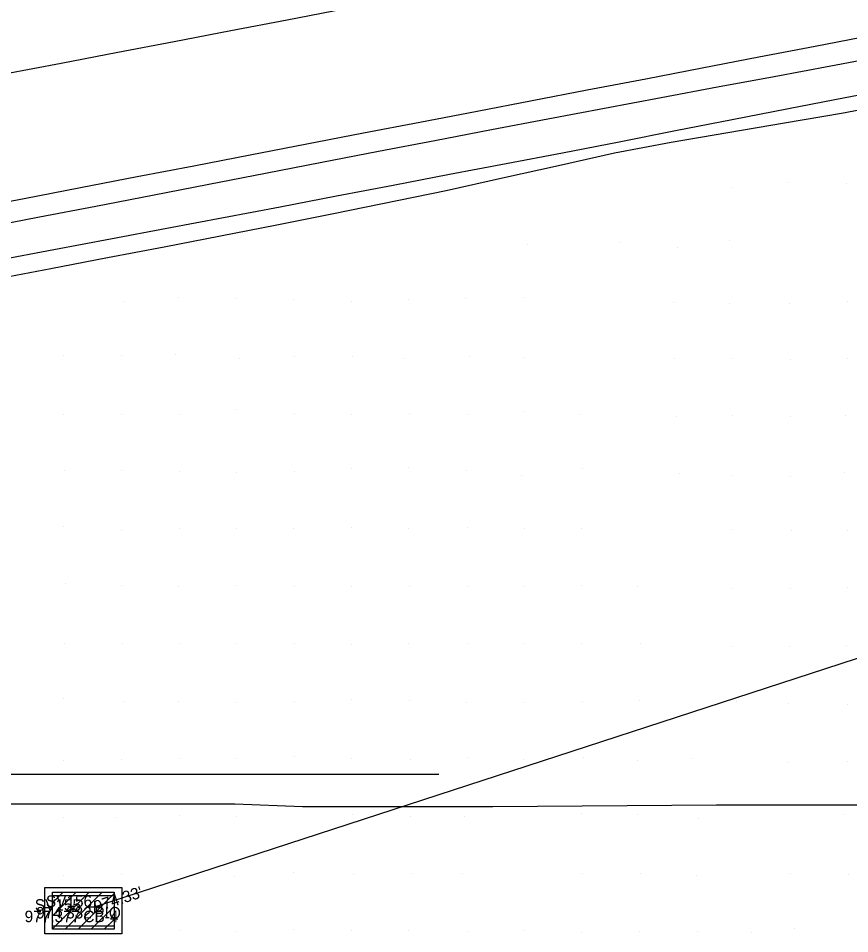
# Model space of a CAD drawing. Extents: x 2262025 to 2264532, y 740981 to 742724.
# Drawn here: x 2262948.6 to 2263020.8, y 742045.7 to 742125.3 of the extents above; entities that cross this region are included whole.
import ezdxf

# ---------------------------------------------------------------- set-up
doc = ezdxf.new("R2010")
doc.units = 0
for name, color, linetype in [('DR_X_Storm_Sewer', 7, 'Continuous'), ('GE_X_Alignment_1000_Curve_Data', 7, 'Continuous'), ('GE_X_Alignment_100_Cardinal_Points', 7, 'Continuous'), ('GE_X_Alignment_100_Curve_Data', 7, 'Continuous'), ('Ground Shots', 7, 'Continuous'), ('HY_X_Spring_Cells', 7, 'Continuous'), ('RS_Raster1', 7, 'Continuous'), ('RW_X_CL', 7, 'Continuous'), ('RW_X_CL_1000_Distances', 7, 'Continuous'), ('RW_X_CL_100_Curve_Data', 7, 'Continuous'), ('RW_X_CL_100_Stations', 7, 'Continuous'), ('RW_X_CL_500_Bearings', 7, 'Continuous'), ('SC_Scratch2', 7, 'Continuous'), ('SV_X_Control_Cells_Found', 7, 'Continuous'), ('SV_X_Text_Comment', 7, 'Continuous')]:
    doc.layers.add(name, color=color, linetype=linetype)

msp = doc.modelspace()

# ---------------------------------------------------------------- linework, layer by layer
at = {"layer": 'DR_X_Storm_Sewer'}
msp.add_line((2262955.205, 742048.032), (2263118.436, 742101.27), dxfattribs=at)
at = {"layer": 'GE_X_Alignment_1000_Curve_Data'}
msp.add_lwpolyline([(2262945.528, 742107.036), (2262950.437, 742107.987), (2262955.345, 742108.938), (2262960.254, 742109.889), (2262965.163, 742110.841), (2262970.072, 742111.792), (2262974.98, 742112.743), (2262979.889, 742113.694), (2262984.798, 742114.645), (2262989.706, 742115.597), (2262994.62, 742116.522), (2262999.535, 742117.442), (2263004.449, 742118.362), (2263009.364, 742119.282), (2263014.278, 742120.202), (2263019.193, 742121.122), (2263024.108, 742122.042)], dxfattribs=at)
at = {"layer": 'GE_X_Alignment_100_Cardinal_Points'}
msp.add_lwpolyline([(2262985.13, 742059.549), (2262938.943, 742059.549), (2262935.634, 742059.549), (2262925.641, 742058.739), (2262915.985, 742057.658), (2262904.843, 742055.901), (2262894.984, 742054.009), (2262882.695, 742051.644), (2262877.968, 742050.36), (2262877.968, 742048.671), (2262884.18, 742049.482), (2262893.026, 742051.104), (2262909.232, 742054.077), (2262920.847, 742055.698), (2262925.197, 742056.142), (2262929.094, 742056.605), (2262932.699, 742056.765), (2262937.682, 742056.986), (2262967.426, 742056.986), (2262973.291, 742056.765), (2262989.828, 742056.765), (2263009.27, 742056.896), (2263029.372, 742056.896)], dxfattribs=at)
at = {"layer": 'GE_X_Alignment_100_Curve_Data'}
msp.add_lwpolyline([(2263025.337, 742119.28), (2263020.429, 742118.33), (2263015.52, 742117.378), (2263010.612, 742116.427), (2263005.706, 742115.464), (2263000.801, 742114.495), (2262995.892, 742113.545), (2262990.981, 742112.606), (2262986.07, 742111.668), (2262981.159, 742110.729), (2262976.248, 742109.79), (2262971.337, 742108.851), (2262966.425, 742107.918), (2262961.513, 742106.989), (2262956.6, 742106.059), (2262951.687, 742105.129), (2262946.776, 742104.192)], dxfattribs=at)
at = {"layer": 'Ground Shots'}
for p, q in [((2263015.523, 742110.984), (2263015.523, 742110.984)), ((2263020.585, 742110.899), (2263020.585, 742110.899)), ((2263010.676, 742110.509), (2263010.676, 742110.509)), ((2263010.361, 742105.985), (2263010.361, 742105.985)), ((2262992.804, 742105.616), (2262992.804, 742105.616)), ((2263000.942, 742105.785), (2263000.942, 742105.785)), ((2263005.844, 742105.353), (2263005.844, 742105.353)), ((2262957.724, 742100.621), (2262957.724, 742100.621)), ((2262962.544, 742101.015), (2262962.544, 742101.015)), ((2262967.547, 742100.868), (2262967.547, 742100.868)), ((2262972.485, 742100.841), (2262972.485, 742100.841)), ((2262977.59, 742100.678), (2262977.59, 742100.678)), ((2262982.52, 742100.817), (2262982.52, 742100.817)), ((2262987.454, 742100.918), (2262987.454, 742100.918)), ((2262992.529, 742100.948), (2262992.529, 742100.948)), ((2263005.567, 742100.582), (2263005.567, 742100.582)), ((2263010.359, 742100.455), (2263010.359, 742100.455)), ((2263015.563, 742100.509), (2263015.563, 742100.509)), ((2263020.604, 742100.683), (2263020.604, 742100.683)), ((2262952.535, 742095.955), (2262952.535, 742095.955)), ((2262957.553, 742095.994), (2262957.553, 742095.994)), ((2262962.229, 742096.061), (2262962.229, 742096.061)), ((2262967.805, 742095.66), (2262967.805, 742095.66)), ((2262972.561, 742095.873), (2262972.561, 742095.873)), ((2262977.627, 742095.852), (2262977.627, 742095.852)), ((2262982.16, 742095.717), (2262982.16, 742095.717)), ((2262987.806, 742095.904), (2262987.806, 742095.904)), ((2262992.503, 742095.81), (2262992.503, 742095.81)), ((2263005.65, 742095.725), (2263005.65, 742095.725)), ((2263010.537, 742095.669), (2263010.537, 742095.669)), ((2263015.674, 742095.638), (2263015.674, 742095.638)), ((2263020.614, 742095.723), (2263020.614, 742095.723)), ((2262952.56, 742090.842), (2262952.56, 742090.842)), ((2262957.532, 742090.839), (2262957.532, 742090.839)), ((2262962.598, 742090.846), (2262962.598, 742090.846)), ((2262967.548, 742091.236), (2262967.548, 742091.236)), ((2262972.564, 742090.892), (2262972.564, 742090.892)), ((2262982.623, 742090.884), (2262982.623, 742090.884)), ((2262992.527, 742091.088), (2262992.527, 742091.088)), ((2262997.325, 742090.86), (2262997.325, 742090.86)), ((2262977.589, 742090.792), (2262977.589, 742090.792)), ((2262987.689, 742090.782), (2262987.689, 742090.782)), ((2263005.812, 742090.651), (2263005.812, 742090.651)), ((2263010.665, 742090.763), (2263010.665, 742090.763)), ((2263015.722, 742090.684), (2263015.722, 742090.684)), ((2263020.509, 742090.733), (2263020.509, 742090.733)), ((2262977.539, 742086.152), (2262977.539, 742086.152)), ((2262982.499, 742086.255), (2262982.499, 742086.255)), ((2262997.626, 742086.146), (2262997.626, 742086.146)), ((2262952.592, 742085.918), (2262952.592, 742085.918)), ((2262957.569, 742085.931), (2262957.569, 742085.931)), ((2262962.562, 742085.882), (2262962.562, 742085.882)), ((2262967.595, 742085.827), (2262967.595, 742085.827)), ((2262972.566, 742085.87), (2262972.566, 742085.87)), ((2262987.568, 742085.943), (2262987.568, 742085.943)), ((2262992.357, 742085.555), (2262992.357, 742085.555)), ((2263006.018, 742085.699), (2263006.018, 742085.699)), ((2263010.693, 742085.489), (2263010.693, 742085.489)), ((2263015.732, 742085.437), (2263015.732, 742085.437)), ((2263020.37, 742085.75), (2263020.37, 742085.75)), ((2262952.54, 742081.106), (2262952.54, 742081.106)), ((2262957.538, 742080.756), (2262957.538, 742080.756)), ((2262962.606, 742080.909), (2262962.606, 742080.909)), ((2262967.556, 742080.947), (2262967.556, 742080.947)), ((2262972.518, 742080.926), (2262972.518, 742080.926)), ((2262977.567, 742080.963), (2262977.567, 742080.963)), ((2262982.528, 742080.917), (2262982.528, 742080.917)), ((2262987.648, 742081.031), (2262987.648, 742081.031)), ((2262992.562, 742080.894), (2262992.562, 742080.894)), ((2262997.506, 742080.935), (2262997.506, 742080.935)), ((2263010.65, 742080.807), (2263010.65, 742080.807)), ((2263015.748, 742080.707), (2263015.748, 742080.707)), ((2263020.639, 742080.745), (2263020.639, 742080.745)), ((2262952.659, 742076.138), (2262952.659, 742076.138)), ((2262957.543, 742075.948), (2262957.543, 742075.948)), ((2262962.532, 742075.914), (2262962.532, 742075.914)), ((2262967.563, 742075.926), (2262967.563, 742075.926)), ((2262972.57, 742075.897), (2262972.57, 742075.897)), ((2262977.565, 742075.885), (2262977.565, 742075.885)), ((2262982.616, 742075.881), (2262982.616, 742075.881)), ((2262987.596, 742075.907), (2262987.596, 742075.907)), ((2262992.535, 742075.917), (2262992.535, 742075.917)), ((2262997.526, 742075.956), (2262997.526, 742075.956)), ((2263002.442, 742075.866), (2263002.442, 742075.866)), ((2263010.675, 742075.726), (2263010.675, 742075.726)), ((2263020.639, 742075.794), (2263020.639, 742075.794)), ((2263015.667, 742075.673), (2263015.667, 742075.673)), ((2262972.573, 742070.929), (2262972.573, 742070.929)), ((2262982.541, 742070.919), (2262982.541, 742070.919)), ((2262992.568, 742070.916), (2262992.568, 742070.916)), ((2262997.554, 742070.916), (2262997.554, 742070.916)), ((2262952.642, 742070.89), (2262952.642, 742070.89)), ((2262957.609, 742070.887), (2262957.609, 742070.887)), ((2262962.613, 742070.886), (2262962.613, 742070.886)), ((2262967.531, 742070.892), (2262967.531, 742070.892)), ((2262977.59, 742070.857), (2262977.59, 742070.857)), ((2262987.592, 742070.883), (2262987.592, 742070.883)), ((2263002.617, 742070.902), (2263002.617, 742070.902)), ((2263010.644, 742070.685), (2263010.644, 742070.685)), ((2263015.62, 742070.654), (2263015.62, 742070.654)), ((2263020.577, 742070.724), (2263020.577, 742070.724)), ((2262952.538, 742066.13), (2262952.538, 742066.13)), ((2262957.719, 742065.904), (2262957.719, 742065.904)), ((2262962.518, 742065.843), (2262962.518, 742065.843)), ((2262967.516, 742065.783), (2262967.516, 742065.783)), ((2262972.557, 742065.919), (2262972.557, 742065.919)), ((2262977.506, 742066.018), (2262977.506, 742066.018)), ((2262982.582, 742065.94), (2262982.582, 742065.94)), ((2262987.527, 742065.828), (2262987.527, 742065.828)), ((2262992.556, 742065.83), (2262992.556, 742065.83)), ((2262997.577, 742065.911), (2262997.577, 742065.911)), ((2263002.565, 742065.946), (2263002.565, 742065.946)), ((2263011.025, 742065.855), (2263011.025, 742065.855)), ((2263015.538, 742065.67), (2263015.538, 742065.67)), ((2263020.634, 742065.662), (2263020.634, 742065.662)), ((2262952.499, 742060.72), (2262952.499, 742060.72)), ((2262957.583, 742060.829), (2262957.583, 742060.829)), ((2262962.599, 742060.92), (2262962.599, 742060.92)), ((2262967.591, 742060.916), (2262967.591, 742060.916)), ((2262972.558, 742061.101), (2262972.558, 742061.101)), ((2262977.567, 742060.963), (2262977.567, 742060.963)), ((2262982.647, 742060.871), (2262982.647, 742060.871)), ((2262987.757, 742060.982), (2262987.757, 742060.982)), ((2262992.536, 742060.884), (2262992.536, 742060.884)), ((2262997.725, 742060.993), (2262997.725, 742060.993)), ((2263002.417, 742060.784), (2263002.417, 742060.784)), ((2263007.207, 742060.909), (2263007.207, 742060.909)), ((2263020.602, 742060.629), (2263020.602, 742060.629)), ((2263015.502, 742060.568), (2263015.502, 742060.568)), ((2262952.568, 742055.828), (2262952.568, 742055.828)), ((2262962.602, 742056.001), (2262962.602, 742056.001)), ((2262967.556, 742055.887), (2262967.556, 742055.887)), ((2262977.601, 742056.059), (2262977.601, 742056.059)), ((2262982.66, 742055.878), (2262982.66, 742055.878)), ((2262987.332, 742055.883), (2262987.332, 742055.883)), ((2262997.499, 742056.131), (2262997.499, 742056.131)), ((2263002.401, 742056.05), (2263002.401, 742056.05)), ((2263020.35, 742056.107), (2263020.35, 742056.107)), ((2262957.162, 742055.793), (2262957.162, 742055.793)), ((2263007.671, 742055.757), (2263007.671, 742055.757)), ((2262972.494, 742051.036), (2262972.494, 742051.036)), ((2262952.559, 742050.757), (2262952.559, 742050.757)), ((2262957.592, 742050.842), (2262957.592, 742050.842)), ((2262967.426, 742050.708), (2262967.426, 742050.708)), ((2262977.75, 742050.86), (2262977.75, 742050.86)), ((2262982.867, 742050.898), (2262982.867, 742050.898)), ((2262987.235, 742050.897), (2262987.235, 742050.897)), ((2262997.58, 742050.916), (2262997.58, 742050.916)), ((2263002.63, 742050.977), (2263002.63, 742050.977)), ((2263007.552, 742050.759), (2263007.552, 742050.759)), ((2263015.665, 742050.919), (2263015.665, 742050.919)), ((2263020.715, 742050.844), (2263020.715, 742050.844)), ((2262952.558, 742045.926), (2262952.558, 742045.926)), ((2262957.485, 742045.981), (2262957.485, 742045.981)), ((2262962.686, 742045.946), (2262962.686, 742045.946)), ((2262967.58, 742045.874), (2262967.58, 742045.874)), ((2262972.536, 742046.094), (2262972.536, 742046.094)), ((2262977.587, 742046.027), (2262977.587, 742046.027)), ((2262982.541, 742045.957), (2262982.541, 742045.957)), ((2262987.601, 742045.88), (2262987.601, 742045.88)), ((2262992.621, 742045.996), (2262992.621, 742045.996)), ((2262997.515, 742045.848), (2262997.515, 742045.848)), ((2263002.557, 742045.926), (2263002.557, 742045.926)), ((2263007.59, 742045.914), (2263007.59, 742045.914)), ((2263012.285, 742045.807), (2263012.285, 742045.807)), ((2263016.043, 742046.167), (2263016.043, 742046.167))]:
    msp.add_line(p, q, dxfattribs=at)
at = {"layer": 'RW_X_CL_1000_Distances'}
msp.add_lwpolyline([(2263022.754, 742123.758), (2263017.845, 742122.811), (2263012.935, 742121.865), (2263008.025, 742120.92), (2263003.115, 742119.975), (2262998.013, 742118.992), (2262993.256, 742118.077), (2262988.462, 742117.154), (2262983.476, 742116.194), (2262978.606, 742115.256), (2262973.656, 742114.303), (2262968.747, 742113.358), (2262963.837, 742112.413), (2262958.927, 742111.467), (2262954.017, 742110.522), (2262949.107, 742109.577), (2262944.197, 742108.632)], dxfattribs=at)
at = {"layer": 'RW_X_CL_100_Curve_Data'}
for p, q in [((2262951.584, 742046.141), (2262954.767, 742049.324)), ((2262951.584, 742047.273), (2262953.636, 742049.324)), ((2262951.584, 742048.404), (2262952.504, 742049.324)), ((2262951.584, 742046.141), (2262954.767, 742049.324)), ((2262951.584, 742047.273), (2262953.636, 742049.324)), ((2262951.584, 742048.404), (2262952.504, 742049.324)), ((2262952.669, 742046.095), (2262955.899, 742049.324)), ((2262952.669, 742046.095), (2262955.899, 742049.324)), ((2262953.801, 742046.095), (2262956.918, 742049.212)), ((2262953.801, 742046.095), (2262956.918, 742049.212)), ((2262954.932, 742046.095), (2262956.918, 742048.081)), ((2262954.932, 742046.095), (2262956.918, 742048.081)), ((2262956.063, 742046.095), (2262956.918, 742046.949)), ((2262956.063, 742046.095), (2262956.918, 742046.949))]:
    msp.add_line(p, q, dxfattribs=at)
for points in [[(2262950.918, 742049.71), (2262957.584, 742049.71), (2262957.584, 742045.71), (2262950.918, 742045.71)], [(2262950.918, 742049.71), (2262957.584, 742049.71), (2262957.584, 742045.71), (2262950.918, 742045.71)], [(2262951.584, 742049.324), (2262956.918, 742049.324), (2262956.918, 742046.095), (2262951.584, 742046.095)], [(2262951.584, 742049.324), (2262956.918, 742049.324), (2262956.918, 742046.095), (2262951.584, 742046.095)], [(2262951.584, 742049.043), (2262956.918, 742049.043), (2262956.918, 742046.377), (2262951.584, 742046.377)], [(2262951.584, 742049.043), (2262956.918, 742049.043), (2262956.918, 742046.377), (2262951.584, 742046.377)]]:
    msp.add_lwpolyline(points, close=True, dxfattribs=at)
at = {"layer": 'RW_X_CL_100_Stations'}
for p, q in [((2262954.251, 742049.71), (2262954.251, 742049.71)), ((2262954.251, 742049.71), (2262954.251, 742049.71)), ((2262954.251, 742049.043), (2262954.251, 742049.043)), ((2262954.251, 742049.043), (2262954.251, 742049.043)), ((2262951.584, 742047.71), (2262951.584, 742047.71)), ((2262951.584, 742047.71), (2262951.584, 742047.71)), ((2262954.251, 742047.71), (2262954.251, 742047.71)), ((2262954.251, 742047.71), (2262954.251, 742047.71)), ((2262954.251, 742047.71), (2262954.251, 742047.71)), ((2262954.251, 742047.71), (2262954.251, 742047.71)), ((2262956.918, 742047.71), (2262956.918, 742047.71)), ((2262956.918, 742047.71), (2262956.918, 742047.71)), ((2262954.251, 742046.377), (2262954.251, 742046.377)), ((2262954.251, 742046.377), (2262954.251, 742046.377)), ((2262954.251, 742046.095), (2262954.251, 742046.095)), ((2262954.251, 742046.095), (2262954.251, 742046.095)), ((2262954.251, 742045.71), (2262954.251, 742045.71)), ((2262954.251, 742045.71), (2262954.251, 742045.71))]:
    msp.add_line(p, q, dxfattribs=at)
at = {"layer": 'RW_X_CL_500_Bearings'}
for p, q in [((2262954.705, 742048.032), (2262955.705, 742048.032)), ((2262954.705, 742048.032), (2262955.705, 742048.032)), ((2262955.205, 742048.532), (2262955.205, 742047.532)), ((2262955.205, 742048.532), (2262955.205, 742047.532)), ((2262955.205, 742048.032), (2262955.205, 742048.032)), ((2262955.205, 742048.032), (2262955.205, 742048.032))]:
    msp.add_line(p, q, dxfattribs=at)
at = {"layer": 'SC_Scratch2'}
msp.add_lwpolyline([(2262976.874, 742126.032), (2262971.964, 742125.091), (2262967.053, 742124.15), (2262962.142, 742123.209), (2262957.232, 742122.267), (2262952.321, 742121.326), (2262947.411, 742120.385), (2262942.5, 742119.443), (2262937.589, 742118.502), (2262932.679, 742117.561), (2262927.768, 742116.619), (2262922.861, 742115.662), (2262917.954, 742114.703), (2262913.046, 742113.744), (2262908.139, 742112.784), (2262903.232, 742111.825), (2262898.325, 742110.865), (2262893.418, 742109.906), (2262888.511, 742108.947), (2262883.604, 742107.987), (2262878.697, 742107.028), (2262873.79, 742106.069)], dxfattribs=at)
at = {"layer": 'SV_X_Control_Cells_Found'}
msp.add_lwpolyline([(2262946.529, 742102.57), (2262951.439, 742103.516), (2262956.348, 742104.462), (2262961.258, 742105.407), (2262966.168, 742106.353), (2262971.074, 742107.317), (2262975.978, 742108.294), (2262985.778, 742110.28), (2262990.657, 742111.375), (2262995.535, 742112.47), (2263000.414, 742113.565), (2263005.324, 742114.499), (2263010.254, 742115.336), (2263015.183, 742116.173), (2263020.113, 742117.01), (2263025.025, 742117.94)], dxfattribs=at)

# ---------------------------------------------------------------- texts
at = {"layer": 'HY_X_Spring_Cells'}
for s, p in [('974.332', (2262950.149, 742047.032)), ('974.332', (2262950.149, 742047.032)), ('977.377', (2262949.148, 742046.71)), ('977.377', (2262949.148, 742046.71))]:
    msp.add_text(s, height=1, dxfattribs=at).set_placement(p)
at = {"layer": 'RS_Raster1'}
msp.add_text("974.33'", height=1, rotation=18.0638, dxfattribs=at).set_placement((2262955.36, 742047.557))
at = {"layer": 'RW_X_CL'}
for s, p in [('PIO', (2262955.205, 742047.032)), ('PIO', (2262955.205, 742047.032)), ('CB-4', (2262954.251, 742046.71)), ('CB-4', (2262954.251, 742046.71))]:
    msp.add_text(s, height=1, dxfattribs=at).set_placement(p)
at = {"layer": 'SV_X_Text_Comment'}
for s, p in [('SV155', (2262950.034, 742047.71)), ('SV155', (2262950.034, 742047.71)), ('SV156', (2262950.995, 742048.032)), ('SV156', (2262950.995, 742048.032))]:
    msp.add_text(s, height=1, dxfattribs=at).set_placement(p)

doc.saveas('drawing.dxf')
